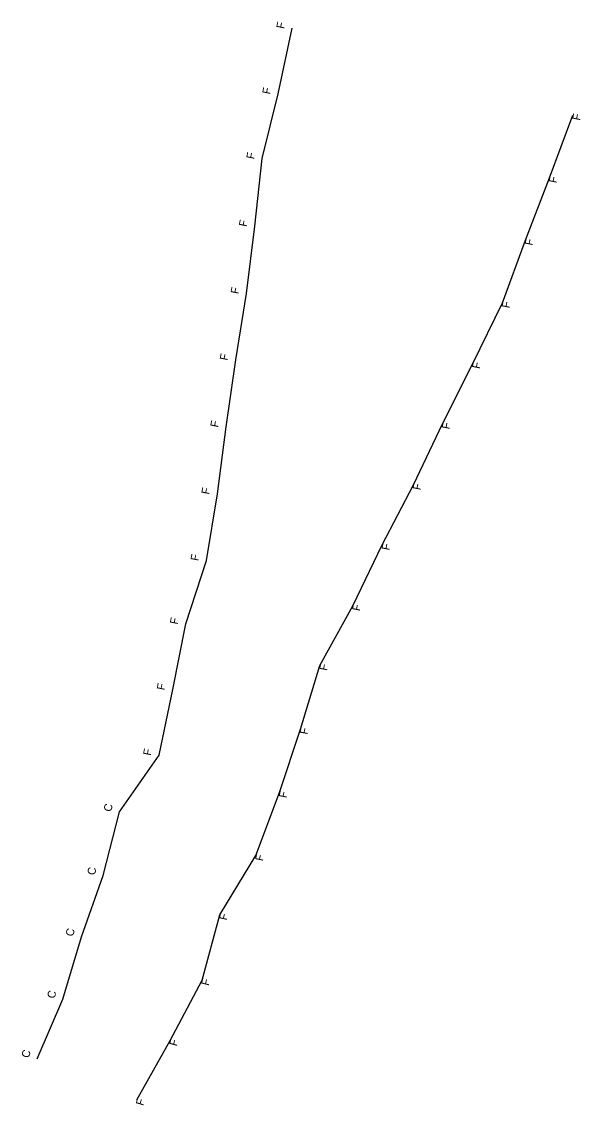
# Model space of a CAD drawing. Extents: x -76 to 2347760, y -10 to 844216.
# Drawn here: x 2347342 to 2347760, y 843404 to 844216 of the extents above; entities that cross this region are included whole.
import ezdxf

# ---------------------------------------------------------------- set-up
doc = ezdxf.new("R2010")
doc.units = 0
for name, color, linetype in [('Prop SS Cut Line', 7, 'Continuous'), ('Prop SS Cut Text', 7, 'Continuous'), ('Prop SS Fill Line', 7, 'Continuous'), ('Prop SS Fill Text', 7, 'Continuous'), ('Prop SS Transition Line', 7, 'Continuous')]:
    doc.layers.add(name, color=color, linetype=linetype)

msp = doc.modelspace()

# ---------------------------------------------------------------- linework, layer by layer
at = {"layer": 'Prop SS Cut Line'}
for p, q in [((2347402.64, 843575.92), (2347415, 843623.6)), ((2347386.4, 843529.87), (2347402.64, 843575.92)), ((2347372.46, 843483.14), (2347386.4, 843529.87)), ((2347353.21, 843438.42), (2347372.46, 843483.14))]:
    msp.add_line(p, q, dxfattribs=at)
at = {"layer": 'Prop SS Fill Line'}
for p, q in [((2347533.88, 844161.87), (2347544.4, 844210.96)), ((2347521.93, 844113.23), (2347533.88, 844161.87)), ((2347736.95, 844098.9), (2347754.56, 844145.78)), ((2347516.36, 844062.61), (2347521.93, 844113.23)), ((2347719.02, 844052.11), (2347736.95, 844098.9)), ((2347510.14, 844012.19), (2347516.36, 844062.61)), ((2347701.7, 844005.13), (2347719.02, 844052.11)), ((2347502.05, 843962.35), (2347510.14, 844012.19)), ((2347679.52, 843959.66), (2347701.7, 844005.13)), ((2347494.97, 843912.19), (2347502.05, 843962.35)), ((2347656.82, 843914.35), (2347679.52, 843959.66)), ((2347488.27, 843861.92), (2347494.97, 843912.19)), ((2347635.02, 843868.76), (2347656.82, 843914.35)), ((2347611.8, 843823.61), (2347635.02, 843868.76)), ((2347480.16, 843812.09), (2347488.27, 843861.92)), ((2347589.72, 843778.11), (2347611.8, 843823.61)), ((2347464.69, 843764.54), (2347480.16, 843812.09)), ((2347565.11, 843733.39), (2347589.72, 843778.11)), ((2347454.87, 843715.23), (2347464.69, 843764.54)), ((2347550.48, 843685.58), (2347565.11, 843733.39)), ((2347444.62, 843666.18), (2347454.87, 843715.23)), ((2347534.8, 843637.98), (2347550.48, 843685.58)), ((2347517.12, 843590.75), (2347534.8, 843637.98)), ((2347490.14, 843546.46), (2347517.12, 843590.75)), ((2347476.76, 843497.5), (2347490.14, 843546.46)), ((2347452.94, 843452.24), (2347476.76, 843497.5)), ((2347427.95, 843407.76), (2347452.94, 843452.24))]:
    msp.add_line(p, q, dxfattribs=at)
at = {"layer": 'Prop SS Transition Line'}
msp.add_line((2347415, 843623.6), (2347444.62, 843666.18), dxfattribs=at)

# ---------------------------------------------------------------- texts
at = {"layer": 'Prop SS Cut Text'}
for s, rotation, p in [('F', 78.77031, (2347538.17, 844210.19)), ('F', 78.77031, (2347527.64, 844161.1)), ('F', 78.77031, (2347515.69, 844112.46)), ('F', 78.77031, (2347510.12, 844061.84)), ('F', 78.77031, (2347503.9, 844011.42)), ('F', 78.77031, (2347495.81, 843961.58)), ('F', 78.77031, (2347488.73, 843911.42)), ('F', 78.77031, (2347482.04, 843861.15)), ('F', 78.77031, (2347473.93, 843811.31)), ('F', 78.77031, (2347458.45, 843763.76)), ('F', 78.77031, (2347448.64, 843714.46)), ('F', 78.62968, (2347438.39, 843665.43)), ('C', 78.1705, (2347408.85, 843623.35)), ('C', 77.39213, (2347396.49, 843575.76)), ('C', 76.29463, (2347380.25, 843529.82)), ('C', 74.99563, (2347366.31, 843483.24)), ('C', 73.69345, (2347347.06, 843438.66))]:
    msp.add_text(s, height=6, rotation=rotation, dxfattribs=at).set_placement(p)
at = {"layer": 'Prop SS Fill Text'}
for rotation, p in [(78.77031, (2347759.78, 844141.46)), (78.77031, (2347742.17, 844094.57)), (78.77031, (2347724.24, 844047.78)), (78.77031, (2347706.93, 844000.8)), (78.77031, (2347684.75, 843955.33)), (78.77031, (2347662.04, 843910.02)), (78.77031, (2347640.25, 843864.43)), (78.77031, (2347617.02, 843819.29)), (78.77031, (2347594.95, 843773.78)), (78.77031, (2347570.33, 843729.07)), (78.77031, (2347555.7, 843681.26)), (78.62968, (2347540.01, 843633.64)), (78.1705, (2347522.3, 843586.37)), (77.39213, (2347495.26, 843542.01)), (76.29463, (2347481.8, 843492.95)), (74.99563, (2347457.87, 843447.58)), (73.69345, (2347432.77, 843402.99))]:
    msp.add_text('F', height=6, rotation=rotation, dxfattribs=at).set_placement(p)

doc.saveas('drawing.dxf')
